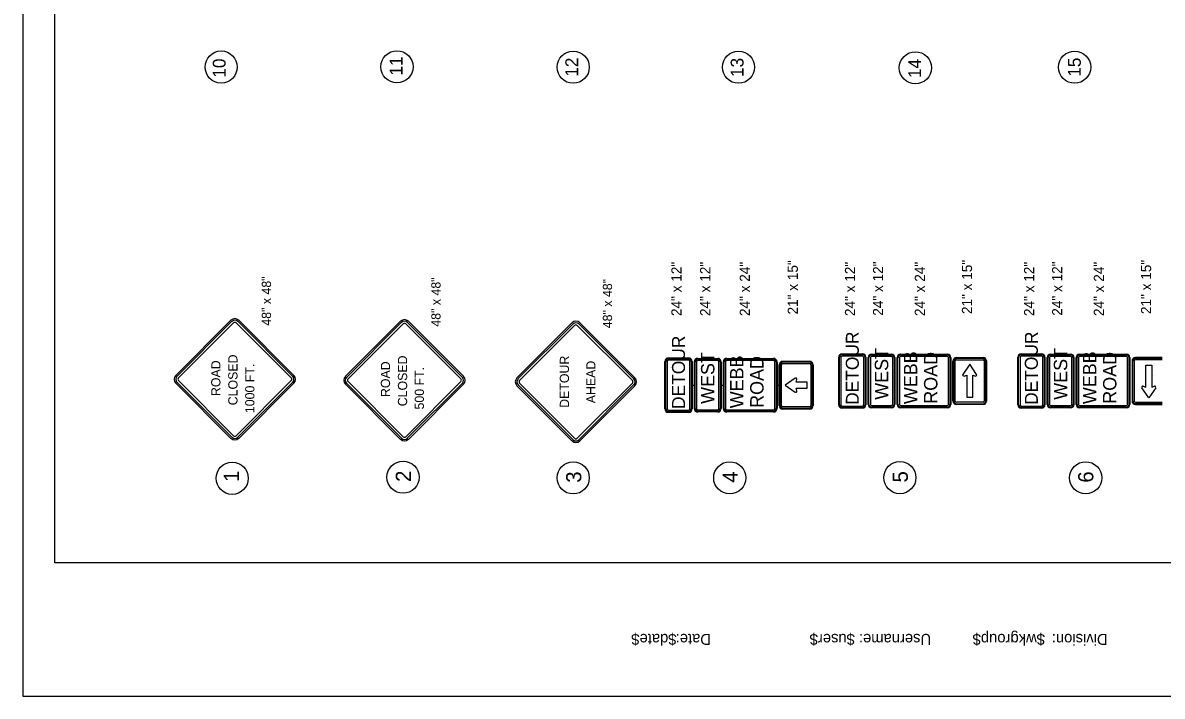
# Model space of a CAD drawing. Extents: x 1123038 to 1172987, y 554419 to 623636.
# Drawn here: x 1149904 to 1163721, y 589308 to 597473 of the extents above; entities that cross this region are included whole.
import ezdxf

# ---------------------------------------------------------------- set-up
doc = ezdxf.new("R2010")
doc.units = 0
for name, color, linetype in [('BORDER', 7, 'Continuous'), ('D_Text_Standard', 7, 'Continuous'), ('Default', 7, 'Continuous'), ('PLOT BOUNDARY', 7, 'Continuous'), ('SIGNS TRAFFIC', 7, 'Continuous')]:
    doc.layers.add(name, color=color, linetype=linetype)

msp = doc.modelspace()

# ---------------------------------------------------------------- linework, layer by layer
at = {"layer": 'BORDER'}
msp.add_lwpolyline([(1150292, 590926), (1150292, 622926), (1171292, 622926), (1171292, 590926)], close=True, dxfattribs=at)
at = {"layer": 'D_Text_Standard'}
for p, q in [((1158021, 593079), (1158048, 593079)), ((1158373, 593079), (1158400, 593079)), ((1159050, 593079), (1159077, 593079))]:
    msp.add_line(p, q, dxfattribs=at)
for centre in [(1152310, 596936), (1154442, 596939), (1156579, 596934), (1158583, 596934), (1160728, 596927), (1162659, 596934), (1152444, 591950), (1154515, 591963), (1156579, 591955), (1158477, 591956), (1160540, 591958), (1162793, 591956)]:
    msp.add_circle(centre, 195, dxfattribs=at)
at = {"layer": 'PLOT BOUNDARY'}
msp.add_lwpolyline([(1171904, 589308), (1171904, 623308), (1149904, 623308), (1149904, 589308)], close=True, dxfattribs=at)
at = {"layer": 'SIGNS TRAFFIC'}
for p, q in [((1159087, 593326), (1159087, 592831)), ((1161194, 593372), (1161194, 592885)), ((1163366, 592885), (1163366, 593372)), ((1163523, 593056), (1163523, 593321)), ((1163523, 593321), (1163594, 593321)), ((1163594, 593321), (1163594, 593056)), ((1161318, 593190), (1161352, 593201)), ((1161352, 593201), (1161352, 592935)), ((1161423, 592935), (1161423, 593201)), ((1161423, 593201), (1161456, 593190)), ((1159281, 593115), (1159292, 593148)), ((1159417, 593115), (1159281, 593115)), ((1159292, 593009), (1159281, 593042)), ((1159281, 593042), (1159417, 593042)), ((1159417, 593042), (1159417, 593115)), ((1163490, 593066), (1163523, 593056)), ((1163594, 593056), (1163627, 593066)), ((1161352, 592935), (1161423, 592935))]:
    msp.add_line(p, q, dxfattribs=at)
for points in [[(1152428, 593866), (1151760, 593198)], [(1152441, 593853), (1151773, 593185)], [(1153178, 593185), (1152510, 593853)], [(1153192, 593198), (1152524, 593866)], [(1154485, 593854), (1153817, 593186)], [(1155248, 593186), (1154580, 593854)], [(1151792, 593166), (1152460, 593834)], [(1152492, 593834), (1153160, 593166)], [(1154498, 593841), (1153830, 593173)], [(1153848, 593154), (1154517, 593822)], [(1154548, 593822), (1155217, 593154)], [(1155235, 593173), (1154567, 593841)], [(1156564, 593835), (1155896, 593167)], [(1156577, 593822), (1155909, 593154)], [(1155928, 593135), (1156596, 593803)], [(1156628, 593803), (1157296, 593135)], [(1157314, 593154), (1156646, 593822)], [(1157328, 593167), (1156660, 593835)], [(1159839, 593458), (1160087, 593458)], [(1159839, 593458), (1160087, 593458)], [(1159839, 593448), (1160087, 593448)], [(1160196, 593453), (1160439, 593453)], [(1160196, 593453), (1160439, 593453)], [(1160196, 593443), (1160439, 593443)], [(1160548, 593453), (1161116, 593453)], [(1160548, 593453), (1161116, 593453)], [(1160548, 593443), (1161116, 593443)], [(1162011, 593458), (1162258, 593458)], [(1162011, 593458), (1162258, 593458)], [(1162011, 593448), (1162258, 593448)], [(1162367, 593453), (1162611, 593453)], [(1162367, 593453), (1162611, 593453)], [(1162367, 593443), (1162611, 593443)], [(1162719, 593453), (1163288, 593453)], [(1162719, 593453), (1163288, 593453)], [(1162719, 593443), (1163288, 593443)], [(1157691, 592790), (1157691, 593367)], [(1157691, 592790), (1157691, 593367)], [(1157701, 592790), (1157701, 593367)], [(1157718, 593367), (1157718, 592790)], [(1157732, 593409), (1157979, 593409)], [(1157732, 593409), (1157979, 593409)], [(1157732, 593398), (1157979, 593398)], [(1157979, 593381), (1157732, 593381)], [(1157993, 592790), (1157993, 593367)], [(1158010, 593367), (1158010, 592790)], [(1158021, 593367), (1158021, 592790)], [(1158021, 593367), (1158021, 592790)], [(1158048, 592794), (1158048, 593363)], [(1158048, 592794), (1158048, 593363)], [(1158058, 592794), (1158058, 593363)], [(1158075, 593363), (1158075, 592794)], [(1158088, 593404), (1158332, 593404)], [(1158088, 593404), (1158332, 593404)], [(1158088, 593393), (1158332, 593393)], [(1158332, 593376), (1158088, 593376)], [(1158345, 592794), (1158345, 593363)], [(1158362, 593363), (1158362, 592794)], [(1158373, 593363), (1158373, 592794)], [(1158373, 593363), (1158373, 592794)], [(1158400, 592794), (1158400, 593363)], [(1158400, 592794), (1158400, 593363)], [(1158410, 592794), (1158410, 593363)], [(1158427, 593363), (1158427, 592794)], [(1158440, 593404), (1159009, 593404)], [(1158440, 593404), (1159009, 593404)], [(1158440, 593393), (1159009, 593393)], [(1159009, 593376), (1158440, 593376)], [(1159022, 592794), (1159022, 593363)], [(1159039, 593363), (1159039, 592794)], [(1159050, 593363), (1159050, 592794)], [(1159050, 593363), (1159050, 592794)], [(1159077, 592831), (1159077, 593326)], [(1159077, 593326), (1159077, 592831)], [(1159104, 592831), (1159104, 593326)], [(1159118, 593367), (1159448, 593367)], [(1159448, 593367), (1159118, 593367)], [(1159448, 593357), (1159118, 593357)], [(1159118, 593340), (1159448, 593340)], [(1159462, 593326), (1159462, 592831)], [(1159479, 592831), (1159479, 593326)], [(1159489, 593326), (1159489, 592831)], [(1159489, 592831), (1159489, 593326)], [(1159798, 592840), (1159798, 593417)], [(1159798, 592840), (1159798, 593417)], [(1159808, 592840), (1159808, 593417)], [(1159826, 593417), (1159826, 592840)], [(1160087, 593431), (1159839, 593431)], [(1160101, 592840), (1160101, 593417)], [(1160118, 593417), (1160118, 592840)], [(1160128, 593417), (1160128, 592840)], [(1160128, 593417), (1160128, 592840)], [(1160155, 592844), (1160155, 593413)], [(1160155, 592844), (1160155, 593413)], [(1160165, 592844), (1160165, 593413)], [(1160182, 593413), (1160182, 592844)], [(1160439, 593426), (1160196, 593426)], [(1160453, 592844), (1160453, 593413)], [(1160470, 593413), (1160470, 592844)], [(1160480, 593413), (1160480, 592844)], [(1160480, 593413), (1160480, 592844)], [(1160507, 592844), (1160507, 593413)], [(1160507, 592844), (1160507, 593413)], [(1160517, 592844), (1160517, 593413)], [(1160534, 593413), (1160534, 592844)], [(1161116, 593426), (1160548, 593426)], [(1161130, 592844), (1161130, 593413)], [(1161147, 593413), (1161147, 592844)], [(1161157, 593413), (1161157, 592844)], [(1161157, 593413), (1161157, 592844)], [(1161184, 592885), (1161184, 593372)], [(1161211, 592885), (1161211, 593372)], [(1161225, 593413), (1161550, 593413)], [(1161550, 593403), (1161225, 593403)], [(1161225, 593386), (1161550, 593386)], [(1161470, 593210), (1161387, 593332), (1161304, 593210)], [(1161563, 593372), (1161563, 592885)], [(1161580, 592885), (1161580, 593372)], [(1161590, 593372), (1161590, 592885)], [(1161969, 592840), (1161969, 593417)], [(1161969, 592840), (1161969, 593417)], [(1161980, 592840), (1161980, 593417)], [(1161997, 593417), (1161997, 592840)], [(1162258, 593431), (1162011, 593431)], [(1162272, 592840), (1162272, 593417)], [(1162289, 593417), (1162289, 592840)], [(1162299, 593417), (1162299, 592840)], [(1162299, 593417), (1162299, 592840)], [(1162326, 592844), (1162326, 593413)], [(1162326, 592844), (1162326, 593413)], [(1162337, 592844), (1162337, 593413)], [(1162354, 593413), (1162354, 592844)], [(1162611, 593426), (1162367, 593426)], [(1162624, 592844), (1162624, 593413)], [(1162641, 593413), (1162641, 592844)], [(1162651, 593413), (1162651, 592844)], [(1162651, 593413), (1162651, 592844)], [(1162678, 592844), (1162678, 593413)], [(1162678, 592844), (1162678, 593413)], [(1162689, 592844), (1162689, 593413)], [(1162706, 593413), (1162706, 592844)], [(1163288, 593426), (1162719, 593426)], [(1163301, 592844), (1163301, 593413)], [(1163318, 593413), (1163318, 592844)], [(1163328, 593413), (1163328, 592844)], [(1163328, 593413), (1163328, 592844)], [(1163355, 593372), (1163355, 592885)], [(1163383, 593372), (1163383, 592885)], [(1163721, 593413), (1163396, 593413)], [(1163396, 593403), (1163721, 593403)], [(1163721, 593386), (1163396, 593386)], [(1159272, 593163), (1159149, 593079), (1159272, 592994)], [(1163616, 593197), (1163615, 593197)], [(1151760, 593103), (1152428, 592434)], [(1151773, 593116), (1152441, 592448)], [(1152460, 592466), (1151792, 593134)], [(1153160, 593134), (1152492, 592466)], [(1152510, 592448), (1153178, 593116)], [(1152524, 592434), (1153192, 593103)], [(1153817, 593091), (1154485, 592422)], [(1153830, 593104), (1154498, 592436)], [(1154517, 592454), (1153848, 593122)], [(1155217, 593122), (1154548, 592454)], [(1154567, 592436), (1155235, 593104)], [(1154580, 592422), (1155248, 593091)], [(1155896, 593071), (1156564, 592403)], [(1155909, 593085), (1156577, 592416)], [(1156596, 592435), (1155928, 593103)], [(1157296, 593103), (1156628, 592435)], [(1156646, 592416), (1157314, 593085)], [(1156660, 592403), (1157328, 593071)], [(1161444, 593059), (1161444, 593059)], [(1163642, 593047), (1163559, 592925), (1163475, 593047)], [(1157732, 592776), (1157979, 592776)], [(1157979, 592759), (1157732, 592759)], [(1157979, 592749), (1157732, 592749)], [(1157979, 592749), (1157732, 592749)], [(1158088, 592781), (1158332, 592781)], [(1158332, 592764), (1158088, 592764)], [(1158332, 592754), (1158088, 592754)], [(1158332, 592754), (1158088, 592754)], [(1158440, 592781), (1159009, 592781)], [(1159009, 592764), (1158440, 592764)], [(1159009, 592754), (1158440, 592754)], [(1159009, 592754), (1158440, 592754)], [(1159448, 592817), (1159118, 592817)], [(1159118, 592800), (1159448, 592800)], [(1159448, 592790), (1159118, 592790)], [(1159118, 592790), (1159448, 592790)], [(1159839, 592826), (1160087, 592826)], [(1160087, 592809), (1159839, 592809)], [(1160087, 592798), (1159839, 592798)], [(1160087, 592798), (1159839, 592798)], [(1160196, 592831), (1160439, 592831)], [(1160439, 592814), (1160196, 592814)], [(1160439, 592803), (1160196, 592803)], [(1160439, 592803), (1160196, 592803)], [(1160548, 592831), (1161116, 592831)], [(1161116, 592814), (1160548, 592814)], [(1161116, 592803), (1160548, 592803)], [(1161116, 592803), (1160548, 592803)], [(1161550, 592871), (1161225, 592871)], [(1161225, 592854), (1161550, 592854)], [(1161550, 592844), (1161225, 592844)], [(1162011, 592826), (1162258, 592826)], [(1162258, 592809), (1162011, 592809)], [(1162258, 592798), (1162011, 592798)], [(1162258, 592798), (1162011, 592798)], [(1162367, 592831), (1162611, 592831)], [(1162611, 592814), (1162367, 592814)], [(1162611, 592803), (1162367, 592803)], [(1162611, 592803), (1162367, 592803)], [(1162719, 592831), (1163288, 592831)], [(1163288, 592814), (1162719, 592814)], [(1163288, 592803), (1162719, 592803)], [(1163288, 592803), (1162719, 592803)], [(1163396, 592871), (1163721, 592871)], [(1163721, 592854), (1163396, 592854)], [(1163396, 592844), (1163721, 592844)]]:
    msp.add_lwpolyline(points, dxfattribs=at)
for centre, radius, start, end in [((1152476, 593818), 67.5, 45, 135), ((1152476, 593818), 48.7, 45, 135), ((1154533, 593806), 67.5, 45, 135), ((1154533, 593806), 48.7, 45, 135), ((1156612, 593787), 67.5, 45, 135), ((1152476, 593818), 22.5, 45, 135), ((1154533, 593806), 22.5, 45, 135), ((1156612, 593787), 48.7, 45, 135), ((1156612, 593787), 22.5, 45, 135), ((1159839, 593417), 41.2, 90, 180), ((1159839, 593417), 41.2, 90, 180), ((1159839, 593417), 30.9, 90, 180), ((1160087, 593417), 41.2, 360, 90), ((1160087, 593417), 41.2, 360, 90), ((1160087, 593417), 30.9, 360, 90), ((1160196, 593413), 40.6, 90, 180), ((1160196, 593413), 40.6, 90, 180), ((1160196, 593413), 30.5, 90, 180), ((1160439, 593413), 40.6, 360, 90), ((1160439, 593413), 40.6, 360, 90), ((1160439, 593413), 30.5, 360, 90), ((1160548, 593413), 40.6, 90, 180), ((1160548, 593413), 40.6, 90, 180), ((1160548, 593413), 30.5, 90, 180), ((1161116, 593413), 40.6, 360, 90), ((1161116, 593413), 40.6, 360, 90), ((1161116, 593413), 30.5, 360, 90), ((1162011, 593417), 41.2, 90, 180), ((1162011, 593417), 41.2, 90, 180), ((1162011, 593417), 30.9, 90, 180), ((1162258, 593417), 41.2, 360, 90), ((1162258, 593417), 41.2, 360, 90), ((1162258, 593417), 30.9, 360, 90), ((1162367, 593413), 40.6, 90, 180), ((1162367, 593413), 40.6, 90, 180), ((1162367, 593413), 30.5, 90, 180), ((1162611, 593413), 40.6, 360, 90), ((1162611, 593413), 40.6, 360, 90), ((1162611, 593413), 30.5, 360, 90), ((1162719, 593413), 40.6, 90, 180), ((1162719, 593413), 40.6, 90, 180), ((1162719, 593413), 30.5, 90, 180), ((1163288, 593413), 40.6, 360, 90), ((1163288, 593413), 40.6, 360, 90), ((1163288, 593413), 30.5, 360, 90), ((1157732, 593367), 41.2, 90, 180), ((1157732, 593367), 41.2, 90, 180), ((1157732, 593367), 30.9, 90, 180), ((1157732, 593367), 13.7, 90, 180), ((1157979, 593367), 41.2, 360, 90), ((1157979, 593367), 41.2, 360, 90), ((1157979, 593367), 30.9, 360, 90), ((1157979, 593367), 13.7, 360, 90), ((1158088, 593363), 40.6, 90, 180), ((1158088, 593363), 40.6, 90, 180), ((1158088, 593363), 30.5, 90, 180), ((1158088, 593363), 13.5, 90, 180), ((1158332, 593363), 40.6, 360, 90), ((1158332, 593363), 40.6, 360, 90), ((1158332, 593363), 30.5, 360, 90), ((1158332, 593363), 13.5, 360, 90), ((1158440, 593363), 40.6, 90, 180), ((1158440, 593363), 40.6, 90, 180), ((1158440, 593363), 30.5, 90, 180), ((1158440, 593363), 13.5, 90, 180), ((1159009, 593363), 40.6, 360, 90), ((1159009, 593363), 40.6, 360, 90), ((1159009, 593363), 30.5, 360, 90), ((1159009, 593363), 13.5, 360, 90), ((1159118, 593326), 41.2, 90, 180), ((1159118, 593326), 41.2, 90, 180), ((1159118, 593326), 30.9, 90, 180), ((1159118, 593326), 13.7, 90, 180), ((1159448, 593326), 41.2, 360, 90), ((1159448, 593326), 41.2, 360, 90), ((1159448, 593326), 30.9, 360, 90), ((1159448, 593326), 13.7, 360, 90), ((1159839, 593417), 13.7, 90, 180), ((1160087, 593417), 13.7, 360, 90), ((1160196, 593413), 13.5, 90, 180), ((1160439, 593413), 13.5, 360, 90), ((1160548, 593413), 13.5, 90, 180), ((1161116, 593413), 13.5, 360, 90), ((1161225, 593372), 40.6, 90, 180), ((1161225, 593372), 30.5, 90, 180), ((1161225, 593372), 13.5, 90, 180), ((1161550, 593372), 40.6, 360, 90), ((1161550, 593372), 30.5, 360, 90), ((1161550, 593372), 13.5, 360, 90), ((1162011, 593417), 13.7, 90, 180), ((1162258, 593417), 13.7, 360, 90), ((1162367, 593413), 13.5, 90, 180), ((1162611, 593413), 13.5, 360, 90), ((1162719, 593413), 13.5, 90, 180), ((1163288, 593413), 13.5, 360, 90), ((1163396, 593372), 40.6, 90, 180), ((1163396, 593372), 30.5, 90, 180), ((1163396, 593372), 13.5, 90, 180), ((1151808, 593150), 67.5, 135, 225), ((1151808, 593150), 48.7, 135, 225), ((1151808, 593150), 22.5, 135, 225), ((1153144, 593150), 22.5, 315, 45), ((1153144, 593150), 48.7, 315, 45), ((1153144, 593150), 67.5, 315, 45), ((1153864, 593138), 67.5, 135, 225), ((1153864, 593138), 48.7, 135, 225), ((1155201, 593138), 48.7, 315, 45), ((1155201, 593138), 67.5, 315, 45), ((1155944, 593119), 67.5, 135, 225), ((1157280, 593119), 67.5, 315, 45), ((1159280, 593152), 12.9, 342.1872, 124.3237), ((1161314, 593203), 12.7, 145.6763, 287.8128), ((1161460, 593203), 12.7, 252.1872, 34.3237), ((1153864, 593138), 22.5, 135, 225), ((1155201, 593138), 22.5, 315, 45), ((1155944, 593119), 48.7, 135, 225), ((1155944, 593119), 22.5, 135, 225), ((1157280, 593119), 22.5, 315, 45), ((1157280, 593119), 48.7, 315, 45), ((1163486, 593054), 12.7, 72.1872, 214.3237), ((1163631, 593054), 12.7, 325.6763, 107.8128), ((1159280, 593005), 12.9, 235.6763, 17.8128), ((1161225, 592885), 40.6, 180, 270), ((1161225, 592885), 30.5, 180, 270), ((1161225, 592885), 13.5, 180, 270), ((1161550, 592885), 40.6, 270, 0), ((1161550, 592885), 30.5, 270, 0), ((1161550, 592885), 13.5, 270, 0), ((1163396, 592885), 40.6, 180, 270), ((1163396, 592885), 30.5, 180, 270), ((1163396, 592885), 13.5, 180, 270), ((1157732, 592790), 41.2, 180, 270), ((1157732, 592790), 41.2, 180, 270), ((1157732, 592790), 30.9, 180, 270), ((1157732, 592790), 13.7, 180, 270), ((1157979, 592790), 41.2, 270, 360), ((1157979, 592790), 41.2, 270, 360), ((1157979, 592790), 30.9, 270, 360), ((1157979, 592790), 13.7, 270, 360), ((1158088, 592794), 40.6, 180, 270), ((1158088, 592794), 40.6, 180, 270), ((1158088, 592794), 30.5, 180, 270), ((1158088, 592794), 13.5, 180, 270), ((1158332, 592794), 40.6, 270, 360), ((1158332, 592794), 40.6, 270, 360), ((1158332, 592794), 30.5, 270, 360), ((1158332, 592794), 13.5, 270, 360), ((1158440, 592794), 40.6, 180, 270), ((1158440, 592794), 40.6, 180, 270), ((1158440, 592794), 30.5, 180, 270), ((1158440, 592794), 13.5, 180, 270), ((1159009, 592794), 40.6, 270, 360), ((1159009, 592794), 40.6, 270, 360), ((1159009, 592794), 30.5, 270, 360), ((1159009, 592794), 13.5, 270, 360), ((1159118, 592831), 41.2, 180, 270), ((1159118, 592831), 41.2, 180, 270), ((1159118, 592831), 30.9, 180, 270), ((1159118, 592831), 13.7, 180, 270), ((1159448, 592831), 41.2, 270, 0), ((1159448, 592831), 41.2, 270, 0), ((1159448, 592831), 30.9, 270, 0), ((1159448, 592831), 13.7, 270, 0), ((1159839, 592840), 41.2, 180, 270), ((1159839, 592840), 41.2, 180, 270), ((1159839, 592840), 30.9, 180, 270), ((1159839, 592840), 13.7, 180, 270), ((1160087, 592840), 41.2, 270, 360), ((1160087, 592840), 41.2, 270, 360), ((1160087, 592840), 30.9, 270, 360), ((1160087, 592840), 13.7, 270, 360), ((1160196, 592844), 40.6, 180, 270), ((1160196, 592844), 40.6, 180, 270), ((1160196, 592844), 30.5, 180, 270), ((1160196, 592844), 13.5, 180, 270), ((1160439, 592844), 40.6, 270, 360), ((1160439, 592844), 40.6, 270, 360), ((1160439, 592844), 30.5, 270, 360), ((1160439, 592844), 13.5, 270, 360), ((1160548, 592844), 40.6, 180, 270), ((1160548, 592844), 40.6, 180, 270), ((1160548, 592844), 30.5, 180, 270), ((1160548, 592844), 13.5, 180, 270), ((1161116, 592844), 40.6, 270, 360), ((1161116, 592844), 40.6, 270, 360), ((1161116, 592844), 30.5, 270, 360), ((1161116, 592844), 13.5, 270, 360), ((1162011, 592840), 41.2, 180, 270), ((1162011, 592840), 41.2, 180, 270), ((1162011, 592840), 30.9, 180, 270), ((1162011, 592840), 13.7, 180, 270), ((1162258, 592840), 41.2, 270, 360), ((1162258, 592840), 41.2, 270, 360), ((1162258, 592840), 30.9, 270, 360), ((1162258, 592840), 13.7, 270, 360), ((1162367, 592844), 40.6, 180, 270), ((1162367, 592844), 40.6, 180, 270), ((1162367, 592844), 30.5, 180, 270), ((1162367, 592844), 13.5, 180, 270), ((1162611, 592844), 40.6, 270, 360), ((1162611, 592844), 40.6, 270, 360), ((1162611, 592844), 30.5, 270, 360), ((1162611, 592844), 13.5, 270, 360), ((1162719, 592844), 40.6, 180, 270), ((1162719, 592844), 40.6, 180, 270), ((1162719, 592844), 30.5, 180, 270), ((1162719, 592844), 13.5, 180, 270), ((1163288, 592844), 40.6, 270, 360), ((1163288, 592844), 40.6, 270, 360), ((1163288, 592844), 30.5, 270, 360), ((1163288, 592844), 13.5, 270, 360), ((1152476, 592482), 22.5, 225, 315), ((1152476, 592482), 67.5, 225, 315), ((1152476, 592482), 48.7, 225, 315), ((1154533, 592470), 67.5, 225, 315), ((1154533, 592470), 48.7, 225, 315), ((1154533, 592470), 22.5, 225, 315), ((1156612, 592451), 67.5, 225, 315), ((1156612, 592451), 48.7, 225, 315), ((1156612, 592451), 22.5, 225, 315)]:
    msp.add_arc(centre, radius, start, end, dxfattribs=at)

# ---------------------------------------------------------------- texts
at = {"layer": 'BORDER'}
for s, p in [('$date$', (1157831, 590063)), ('Date:', (1158249, 590063)), ('$user$', (1159994, 590063)), ('Username:', (1160919, 590063)), ('$wkgroup$', (1162299, 590063)), ('Division:', (1163059, 590063))]:
    msp.add_text(s, height=133.9, rotation=180, dxfattribs=at).set_placement(p)
at = {"layer": 'D_Text_Standard'}
for s, height, p in [('10', 156.2, (1152364, 596807)), ('11', 156.2, (1154509, 596833)), ('12', 156.2, (1156639, 596818)), ('13', 156.2, (1158644, 596815)), ('14', 156.2, (1160798, 596802)), ('15', 156.2, (1162734, 596818)), ('24" x 12"', 123.2, (1157892, 593917)), ('24" x 12"', 123.2, (1158241, 593917)), ('24" x 24"', 123.2, (1158721, 593917)), ('21" x 15"', 123.2, (1159303, 593936)), ('24" x 12"', 123.2, (1159997, 593917)), ('24" x 12"', 123.2, (1160337, 593921)), ('24" x 24"', 123.2, (1160844, 593917)), ('21" x 15"', 123.2, (1161415, 593941)), ('24" x 12"', 123.2, (1162169, 593917)), ('24" x 12"', 123.2, (1162509, 593921)), ('24" x 24"', 123.2, (1163015, 593917)), ('21" x 15"', 123.2, (1163587, 593941)), ('48" x 48"', 112, (1152914, 593800)), ('48" x 48"', 112, (1154970, 593788)), ('48" x 48"', 112, (1157050, 593769)), ('1', 184, (1152526, 591907)), ('2', 184, (1154611, 591906)), ('3', 184, (1156677, 591896)), ('4', 184, (1158574, 591897)), ('5', 184, (1160637, 591899)), ('6', 184, (1162886, 591897))]:
    msp.add_text(s, height=height, rotation=90, dxfattribs=at).set_placement(p)
at = {"layer": 'Default'}
for s, height, p in [('ROAD', 0.00033, (1151076, 595034)), ('CLOSED', 0.00033, (1152561, 595034)), ('500 FT', 0.00033, (1154046, 595034)), ('CLOSED', 112, (1152508, 592835)), ('ROAD', 112, (1152301, 592947)), ('1000 FT.', 112, (1152713, 592740)), ('ROAD', 112, (1154358, 592935)), ('CLOSED', 112, (1154565, 592823)), ('DETOUR', 112, (1156528, 592804)), ('AHEAD', 112, (1156849, 592859)), ('500 FT.', 112, (1154769, 592784)), ('ROAD', 0.00033, (1153058, 592831)), ('CLOSED', 0.00033, (1154543, 592831)), ('500 FT', 0.00033, (1156028, 592831))]:
    msp.add_text(s, height=height, rotation=90, dxfattribs=at).set_placement(p)
at = {"layer": 'SIGNS TRAFFIC'}
for s, height, p in [('DETOUR', 157.5, (1160042, 592840)), ('DETOUR', 157.5, (1162213, 592840)), ('DETOUR', 157.5, (1157934, 592790)), ('WEST', 162.5, (1158291, 592852)), ('WEST', 162.5, (1160399, 592902)), ('WEBB', 162.5, (1160751, 592849)), ('ROAD', 162.5, (1160995, 592854)), ('WEST', 162.5, (1162570, 592902)), ('WEBB', 162.5, (1162922, 592849)), ('ROAD', 162.5, (1163166, 592854)), ('WEBB', 162.5, (1158643, 592799)), ('ROAD', 162.5, (1158887, 592804))]:
    msp.add_text(s, height=height, rotation=90, dxfattribs=at).set_placement(p)

doc.saveas('drawing.dxf')
